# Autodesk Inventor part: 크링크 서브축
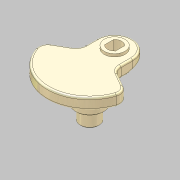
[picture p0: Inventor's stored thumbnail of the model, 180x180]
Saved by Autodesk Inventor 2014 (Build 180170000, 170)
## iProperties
Manager: KYOUNG IL JANG
Company: 한국ATC센터
Created: 2012-10
Part Number: 크링크 서브축
Document SubType Name: Modeling
Density: 1 g/cm^3
Checked By: KYOUNG IL JANG
Vendor: CBT Solutions
Designer: KYOUNG IL JANG
Material: 일반
Appearance: _시험_금속-티타늄(광택)
Author: KYOUNG IL JANG
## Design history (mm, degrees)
sketch "스케치1"
  geometry: L1 (-19, 109.368)-(-19, 91.368); L2 (-19, 91.368)-(-44.545, 76.619); L3 (19, 109.368)-(19, 91.368); L4 (19, 91.368)-(44.545, 76.619); C1 r 32.5 at (0, 83) reference; C2 r 10 at (0, 83); C3 r 17.5 at (0, 83); A1 r 45 centre (0, 83) between (-44.545, 76.619) and (44.545, 76.619); A2 r 32.5 centre (0, 83) between (-19, 109.368) and (19, 109.368); A3 r 19 centre (0, 109.368) between (19, 109.368) and (-19, 109.368); 1 further point
  constraints: 8 end point, 6 point on circle, 5 centre point, 4 coincident, 2 equal length, 1 horizontal alignment, 1 parallel, 1 tangent, 1 vertical, 1 vertical alignment
  dimensions: "d0" = 20 diameter of C2; "d1" = 35 diameter of C3; "d2" = 90 diameter of A1 (derived); "d3" = 65 diameter of A2 (derived); "d4" = 120 deg angle of L3 L4; "d5" = 19 radius of A3 (derived); "d6" = 18 distance of L1.start L1.end (derived)
  node "참조1"
extrude "돌출1" new body sketch "스케치1" distance "d7" = 12; taper "d8" = 0 deg
extrude "돌출2" join sketch "스케치1" distance "d9" = 5; taper "d10" = 0 deg
extrude "돌출3" join sketch "스케치1" distance "d11" = 41; taper "d12" = 0 deg
sketch "스케치2"
  geometry: C1 r 7.5 at (0, 109.368); C2 r 11 at (0, 109.368); A1 r 19 centre (0, 109.368) between (19, 109.368) and (-19, 109.368) reference; 1 further point
  constraints: 2 centre point, 2 coincident
  dimensions: "d13" = 15 diameter of C1; "d14" = 22 diameter of C2
extrude "돌출4" join sketch "스케치2" distance "d15" = 3; taper "d16" = 0 deg
extrude "돌출6" cut sketch "스케치2" stored distance "d19" = 10; taper "d20" = 0 deg
sketch "스케치3"
  geometry: L1 (-5.75, 4.815)-(-5.75, -4.815); L2 (5.75, 4.815)-(5.75, -4.815); A1 r 7.5 centre (0, 0) between (-5.75, 4.815) and (-5.75, -4.815) reference; 1 further point
  constraints: 4 end point, 4 point on circle, 2 parallel, 1 vertical
  dimensions: "d21" = 11.5 distance between parallel lines of L2 L1
extrude "돌출7" join sketch "스케치3" stored distance "d22" = 10; taper "d23" = 0 deg
sketch "스케치4"
  geometry: C1 r 10 at (0, 0) reference; C2 r 15 at (0, 0); 1 further point
  constraints: 1 centre point, 1 coincident
  dimensions: "d30" = 30 diameter of C2
extrude "돌출8" join sketch "스케치4" distance "d28" = 21; taper "d29" = 0 deg
chamfer "모따기1" distance "d31" = 1; stored, may be unused: second distance "d32" = 2, angle "d33" = 45 deg
sketch "스케치5"
  geometry: L1 (-19, 91.368)-(-19, 109.368) reference; L2 (19, 109.368)-(19, 91.368) reference; C1 r 9 at (0, 83); 3 further points
  constraints: 2 point on line, 1 centre point, 1 horizontal alignment
  dimensions: "d34" = 21 vertical distance of point (-19, 104) C1.centre (derived)
node "작업 평면1"
  node "작업축2"
sketch "스케치6"
  geometry: L1 (0, 50)-(38, 50); L2 (38, 50)-(38, 0); L3 (38, 0)-(0, 0); L4 (0, 0)-(0, 50); L5 (0, -12.202)-(0, 5.185) reference; L6 (38, 5.185)-(38, -12.202) reference; 2 further points
  constraints: 8 end point, 2 collinear, 1 point on line
  dimensions: "d37" = 50 distance from line of L1 L3.end
extrude "돌출9" cut sketch "스케치6" stored distance "d38" = 20.7; taper "d39" = 0 deg
fillet "모깎기1" dims "d26" = 10, "d27" = 2
node "솔리드1"
other parameters: "d35" = -15 deg (derived)
